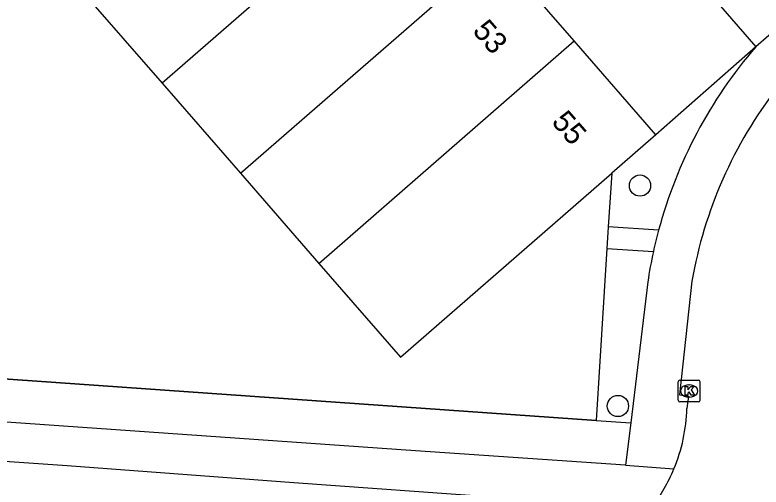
# Model space of a CAD drawing. Extents: x 155888 to 156864, y 383882 to 384671.
# Drawn here: x 156040.51 to 156074.9, y 383999.01 to 384020.77 of the extents above; entities that cross this region are included whole.
import ezdxf

# ---------------------------------------------------------------- set-up
doc = ezdxf.new("R2010")
doc.units = 0
for name, color, linetype in [('IMGEO_Boom', 7, 'Continuous'), ('IMGEO_Groenvoorziening', 7, 'Continuous'), ('IMGEO_Hek', 7, 'Continuous'), ('IMGEO_Kolk', 7, 'Continuous'), ('IMGEO_Pand', 7, 'Continuous'), ('IMGEO_Pand_nummerreeks', 7, 'Continuous'), ('IMGEO_Rijbaan_lokaal_gesloten', 7, 'Continuous'), ('IMGEO_Rijbaan_lokaal_open', 7, 'Continuous'), ('IMGEO_Voetpad_open', 7, 'Continuous')]:
    doc.layers.add(name, color=color, linetype=linetype)

msp = doc.modelspace()

# ---------------------------------------------------------------- linework, layer by layer
at = {"layer": 'IMGEO_Boom'}
for centre in [(156069.316, 384012.903), (156068.297, 384002.747)]:
    msp.add_circle(centre, 0.489, dxfattribs=at)
at = {"layer": 'IMGEO_Groenvoorziening'}
for points in [[(156074.654, 384019.297), (156070.039, 384015.245)], [(156068.011, 384013.475), (156067.854, 384010.996)], [(156067.79, 384009.998), (156067.288, 384002.076)], [(156002.615, 384006.624), (156067.288, 384002.076)], [(156067.288, 384002.076), (156068.886, 384001.964)]]:
    msp.add_lwpolyline(points, dxfattribs=at)
at = {"layer": 'IMGEO_Hek'}
for points in [[(156068.011, 384013.475), (156067.854, 384010.996)], [(156067.854, 384010.996), (156067.79, 384009.998)], [(156067.79, 384009.998), (156067.288, 384002.076)], [(156067.288, 384002.076), (156002.615, 384006.624)]]:
    msp.add_lwpolyline(points, dxfattribs=at)
at = {"layer": 'IMGEO_Kolk'}
for p, q in [((156071.154, 384003.94), (156072.006, 384003.94)), ((156071.079, 384003.014), (156071.079, 384003.866)), ((156071.567, 384003.72), (156071.592, 384003.72)), ((156072.08, 384003.866), (156072.08, 384003.014)), ((156072.006, 384002.94), (156071.154, 384002.94)), ((156071.59, 384003.16), (156071.565, 384003.16))]:
    msp.add_line(p, q, dxfattribs=at)
for points in [[(156071.154, 384003.94), (156072.006, 384003.94)], [(156071.079, 384003.014), (156071.079, 384003.866)], [(156071.4, 384003.64), (156071.523, 384003.64), (156071.523, 384003.489), (156071.653, 384003.64), (156071.817, 384003.64), (156071.671, 384003.489), (156071.824, 384003.24), (156071.672, 384003.24), (156071.587, 384003.404), (156071.523, 384003.337), (156071.523, 384003.24), (156071.4, 384003.24), (156071.4, 384003.64)], [(156072.08, 384003.866), (156072.08, 384003.014)], [(156072.006, 384002.94), (156071.154, 384002.94)]]:
    msp.add_lwpolyline(points, dxfattribs=at)
for centre, start, end in [((156071.156, 384003.864), 91.552, 178.448), ((156071.156, 384003.864), 91.552, 178.448), ((156072.004, 384003.864), 1.552, 88.448), ((156072.004, 384003.864), 1.552, 88.448), ((156071.156, 384003.016), 181.552, 268.448), ((156071.156, 384003.016), 181.552, 268.448), ((156072.004, 384003.016), 271.552, 358.448), ((156072.004, 384003.016), 271.552, 358.448)]:
    msp.add_arc(centre, 0.0765, start, end, dxfattribs=at)
for centre, major_axis, ratio, start_param, end_param in [((156071.566, 384003.44), (-0.387, 0.002), 0.722429, 4.712389, 7.853982), ((156071.591, 384003.44), (-0.39, 0.002), 0.717154, 1.570796, 4.712389)]:
    msp.add_ellipse(centre, major_axis=major_axis, ratio=ratio, start_param=start_param, end_param=end_param, dxfattribs=at)
at = {"layer": 'IMGEO_Pand'}
for points in [[(156059.068, 384027.874), (156047.286, 384017.621)], [(156050.896, 384013.474), (156062.673, 384023.724)], [(156066.285, 384019.566), (156062.673, 384023.724)], [(156043.663, 384021.784), (156047.286, 384017.621)], [(156054.512, 384009.319), (156066.285, 384019.566)], [(156070.039, 384015.245), (156066.285, 384019.566)], [(156047.286, 384017.621), (156050.896, 384013.474)], [(156070.039, 384015.245), (156068.011, 384013.475)], [(156050.896, 384013.474), (156054.512, 384009.319)], [(156054.512, 384009.319), (156058.272, 384004.999), (156068.011, 384013.475)]]:
    msp.add_lwpolyline(points, dxfattribs=at)
at = {"layer": 'IMGEO_Rijbaan_lokaal_gesloten'}
msp.add_lwpolyline([(156071.711, 384008.503), (156071.133, 384003.262), (156071.547, 384003.196), (156071.477, 384002.639)], dxfattribs=at)
for centre, radius, start, end in [((156091.604, 384005.046), 20.191, 142.2272, 170.1429), ((156063.648, 384002.856), 7.832, 337.4262, 358.4095), ((156063.522, 384002.895), 7.963, 323.0045, 337.5198)]:
    msp.add_arc(centre, radius, start, end, dxfattribs=at)
at = {"layer": 'IMGEO_Rijbaan_lokaal_open'}
for points in [[(156041.863, 384057.029), (156074.654, 384019.297)], [(156078.852, 384022.966), (156074.654, 384019.297)]]:
    msp.add_lwpolyline(points, dxfattribs=at)
at = {"layer": 'IMGEO_Voetpad_open'}
for points in [[(156067.854, 384010.996), (156067.79, 384009.998)], [(156070.172, 384010.849), (156067.854, 384010.996)], [(156067.79, 384009.998), (156069.931, 384009.862)], [(156069.673, 384008.462), (156068.886, 384001.964)], [(156068.651, 384000.027), (156058.973, 384000.676), (156010.723, 384004.054), (156000, 384004.803), (155996.725, 384005.017)], [(156000.311, 383999.021), (156000.374, 384000), (156000.561, 384002.935), (156010.577, 384002.245), (156042.911, 384000), (156053.36, 383999.216), (156062.747, 383998.542)], [(156068.886, 384001.964), (156068.651, 384000.027)], [(156068.651, 384000.027), (156070.88, 383999.85)]]:
    msp.add_lwpolyline(points, dxfattribs=at)
for centre, radius, start, end in [((156090.878, 384005.277), 21.443, 139.1672, 164.9373), ((156092.044, 384004.985), 22.645, 164.9929, 167.5638), ((156090.277, 384005.389), 20.832, 167.6003, 171.5164)]:
    msp.add_arc(centre, radius, start, end, dxfattribs=at)

# ---------------------------------------------------------------- texts
at = {"layer": 'IMGEO_Pand_nummerreeks'}
for s, p in [('53', (156061.559, 384020.007)), ('55', (156065.201, 384015.814))]:
    msp.add_text(s, height=1, rotation=310.9819, dxfattribs=at).set_placement(p)

doc.saveas('drawing.dxf')
